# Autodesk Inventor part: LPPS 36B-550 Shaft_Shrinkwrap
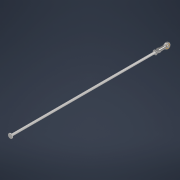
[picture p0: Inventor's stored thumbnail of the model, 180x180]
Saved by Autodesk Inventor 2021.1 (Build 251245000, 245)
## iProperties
Created: 2020-09
Part Number: LPPS 36B-550 Shaft_Shrinkwrap
Material: Generic
Document SubType Name: Modeling
Designer: J. Nielson
Density: 1 g/cm^3
Appearance: Default
Author: J. Nielson
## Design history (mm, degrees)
derived "LPPS 36B-550.iam"
body "Solid1"
node "LPPS-36B-550 ROD.ipt:1"
node "Custom Flanged Nut.ipt:1"
body "Solid2"
node "FEMALE Rod End SW.ipt:1"
body "Solid3"
node "JIS B 1181 - M8x1(4).ipt:1"
body "Solid4"
